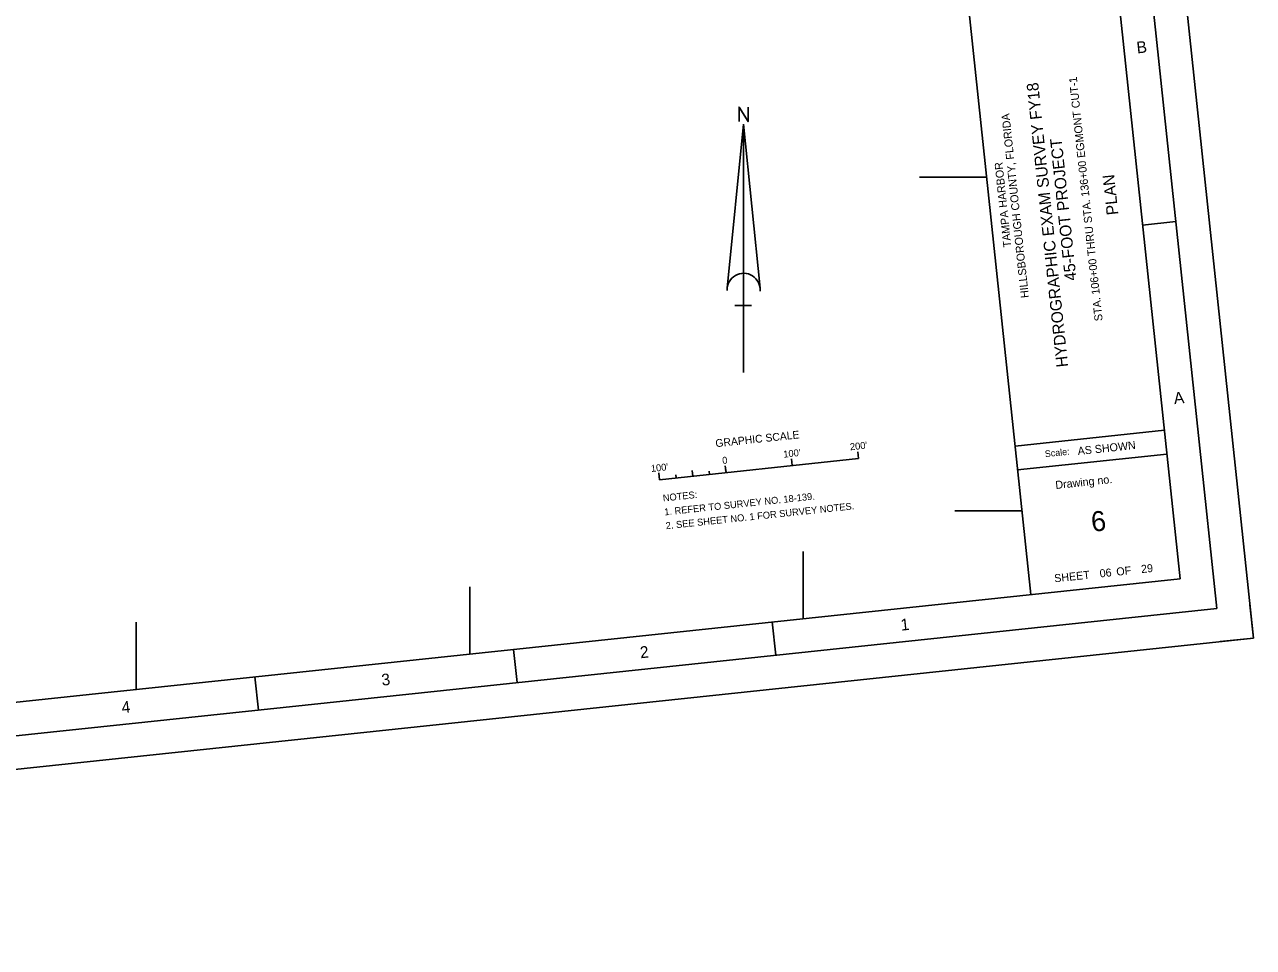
# Model space of a CAD drawing. Extents: x 347441 to 352175, y 1184845 to 1188690.
# Drawn here: x 350332 to 352175, y 1184845 to 1186229 of the extents above; entities that cross this region are included whole.
import ezdxf

# ---------------------------------------------------------------- set-up
doc = ezdxf.new("R2010")
doc.units = 0
for name, color, linetype in [('G-ANNO-NPLT', 7, 'Continuous'), ('G-ANNO-TEXT-DRWG', 7, 'Continuous'), ('G-ANNO-TEXT-PROJ', 7, 'Continuous'), ('G-ANNO-TEXT-TTLB', 7, 'Continuous'), ('G-ANNO-TTLB', 7, 'Continuous'), ('V-ANNO-NOTE', 7, 'Continuous'), ('V-ANNO-SYMB', 7, 'Continuous'), ('V-TOPO-COOR-STAT', 7, 'Continuous')]:
    doc.layers.add(name, color=color, linetype=linetype)

msp = doc.modelspace()

# ---------------------------------------------------------------- linework, layer by layer
at = {"layer": 'G-ANNO-NPLT'}
msp.add_lwpolyline([(347441.2, 1188226.4), (351816.7, 1188690.2), (352175, 1185309.2), (347799.6, 1184845.4)], close=True, dxfattribs=at)
msp.add_lwpolyline([(352169.8, 1185358.9), (352175, 1185309.2), (352125.3, 1185303.9)], dxfattribs=at)
at = {"layer": 'G-ANNO-TTLB'}
for p, q in [((351504, 1188556.5), (351841.3, 1185374.4)), ((352058.6, 1185933.7), (352008.9, 1185928.4)), ((351817.7, 1185596.9), (352041.5, 1185620.6)), ((351821.5, 1185561.4), (352045.2, 1185585.1)), ((351458.8, 1185283.5), (351453.5, 1185333.3)), ((351070.9, 1185242.4), (351065.7, 1185292.2)), ((350683.1, 1185201.3), (350677.9, 1185251))]:
    msp.add_line(p, q, dxfattribs=at)
for points in [[(347844, 1184900.4), (352120.1, 1185353.6), (351772.2, 1188635.2), (347496.2, 1188182)], [(351727.8, 1188580.2), (347625.8, 1188145.4), (347963.1, 1184963.3), (352065.1, 1185398.1)]]:
    msp.add_lwpolyline(points, close=True, dxfattribs=at)
at = {"layer": 'V-ANNO-NOTE'}
for p, q in [((351284.7, 1185546.6), (351583.1, 1185578.2)), ((351483.6, 1185567.7), (351482.5, 1185578.1)), ((351583.1, 1185578.2), (351582, 1185588.6)), ((351284.7, 1185546.6), (351283.6, 1185557)), ((351334.5, 1185551.9), (351333.6, 1185560.4)), ((351359.3, 1185554.5), (351358.8, 1185559.3)), ((351384.2, 1185557.2), (351383.1, 1185567.5)), ((351384.2, 1185557.2), (351383.1, 1185567.5)), ((351384.2, 1185557.2), (351383.6, 1185562.1)), ((351309.6, 1185549.3), (351309.1, 1185554))]:
    msp.add_line(p, q, dxfattribs=at)
at = {"layer": 'V-ANNO-SYMB'}
for p, q in [((351385.9, 1185833.8), (351410.6, 1186079.6)), ((351410.6, 1185707.2), (351410.6, 1186079.6)), ((351435.3, 1185833.8), (351410.6, 1186079.6)), ((351422.4, 1185807.8), (351397.6, 1185807.8))]:
    msp.add_line(p, q, dxfattribs=at)
msp.add_lwpolyline([(351403.8, 1186083.5), (351403.8, 1186105.3), (351417.3, 1186083.5), (351417.3, 1186105.3)], dxfattribs=at)
msp.add_arc((351410.6, 1185831.3), 24.8, 355.2984, 182.0673, dxfattribs=at)
at = {"layer": 'V-TOPO-COOR-STAT'}
for p, q in [((351674.4, 1186000), (351775, 1186000)), ((351727.4, 1185500), (351828, 1185500)), ((351500, 1185338.2), (351500, 1185438.8)), ((351000, 1185285.2), (351000, 1185385.8)), ((350500, 1185232.2), (350500, 1185332.8))]:
    msp.add_line(p, q, dxfattribs=at)

# ---------------------------------------------------------------- texts
at = {"layer": 'G-ANNO-TEXT-DRWG'}
for s, height, rotation, p in [('STA. 106+00 THRU STA. 136+00 EGMONT CUT-1', 12, 96.0506, (351949, 1185784.9)), ('PLAN', 17.5, 96.0506, (351972.6, 1185944.2)), ('6', 30, 6.0506, (351933.2, 1185468.4)), (' 06          29', 12, 6.0506, (351940.7, 1185399.5))]:
    msp.add_text(s, height=height, rotation=rotation, dxfattribs=at).set_placement(p)
at = {"layer": 'G-ANNO-TEXT-PROJ'}
for s, height, p in [('HYDROGRAPHIC EXAM SURVEY FY18', 17.5, (351897.4, 1185716.1)), ('HILLSBOROUGH COUNTY, FLORIDA', 12, (351838.4, 1185819.6)), ('45-FOOT PROJECT', 17.5, (351910, 1185845.8)), ('TAMPA HARBOR', 12, (351812.2, 1185895.6))]:
    msp.add_text(s, height=height, rotation=96.0506, dxfattribs=at).set_placement(p)
at = {"layer": 'G-ANNO-TEXT-TTLB'}
for s, height, p in [('AS SHOWN', 12, (351912.1, 1185583.5)), ('Scale:', 10, (351862.8, 1185580.2)), ('Drawing no.', 12, (351878.7, 1185532.6)), ('SHEET         OF', 12, (351877, 1185392.7))]:
    msp.add_text(s, height=height, rotation=6.0506, dxfattribs=at).set_placement(p)
at = {"layer": 'G-ANNO-TTLB'}
for s, p in [('B', (352000.7, 1186185.6)), ('A', (352056.5, 1185659.8)), ('1', (351647, 1185320.2)), ('2', (351256.1, 1185278.8)), ('3', (350868.5, 1185237.7)), ('4', (350478.8, 1185196.4))]:
    msp.add_text(s, height=17.5, rotation=6.0506, dxfattribs=at).set_placement(p)
at = {"layer": 'V-ANNO-NOTE'}
for s, height, p in [('GRAPHIC SCALE', 11.666, (351368.9, 1185595.3)), ("200'", 10.42, (351570.6, 1185590.6)), ('0', 10.4, (351379.1, 1185570.1)), ("100'", 10.42, (351470.7, 1185579.5)), ("100'", 10.42, (351272.1, 1185558.1)), ('NOTES:', 10.42, (351290, 1185513.8)), ('1. REFER TO SURVEY NO. 18-139.', 10.416, (351292.2, 1185493)), ('2. SEE SHEET NO. 1 FOR SURVEY NOTES.', 10.416, (351294.4, 1185472.3))]:
    msp.add_text(s, height=height, rotation=6.0506, dxfattribs=at).set_placement(p)

doc.saveas('drawing.dxf')
